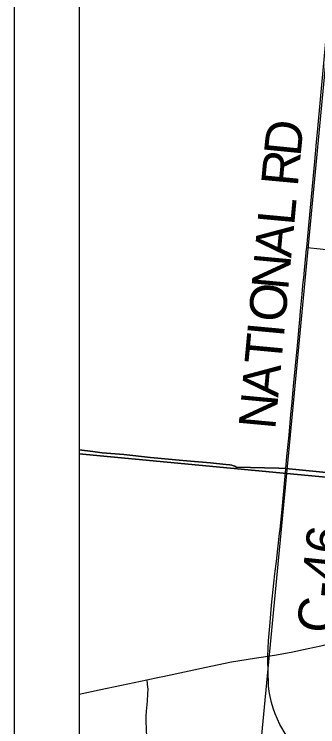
# Model space of a CAD drawing. Extents: x 0 to 34, y 0 to 22.
# Drawn here: x 22.416 to 22.884, y 14.548 to 15.645 of the extents above; entities that cross this region are included whole.
import ezdxf

# ---------------------------------------------------------------- set-up
doc = ezdxf.new("R2010")
doc.units = 0
for name, color, linetype in [('GM_X_City_Street', 7, 'Continuous'), ('GM_X_County_Road', 7, 'Continuous'), ('GM_X_County_Road_Text', 7, 'Continuous'), ('GM_X_Section', 7, 'Continuous'), ('SH_Border', 7, 'Continuous'), ('SH_Data', 7, 'Continuous')]:
    doc.layers.add(name, color=color, linetype=linetype)

msp = doc.modelspace()

# ---------------------------------------------------------------- linework, layer by layer
at = {"layer": 'GM_X_City_Street'}
for points in [[(22.867, 15.2862), (22.8729, 15.2855), (22.8828, 15.2843), (22.9172, 15.281)], [(22.6217, 14.4767), (22.6219, 14.4866), (22.6213, 14.5124), (22.6206, 14.5331), (22.6202, 14.5418), (22.6196, 14.5585), (22.6195, 14.5635), (22.6202, 14.5718), (22.6215, 14.5873), (22.6222, 14.5984), (22.6225, 14.6055), (22.6222, 14.6089), (22.6218, 14.6126), (22.6215, 14.6158), (22.6208, 14.6201)]]:
    msp.add_lwpolyline(points, dxfattribs=at)
at = {"layer": 'GM_X_County_Road'}
msp.add_line((22.6208, 14.6201), (22.6395, 14.6241), dxfattribs=at)
for points in [[(22.5164, 15.9857), (22.5164, 14.9679), (22.8365, 14.9377), (22.9324, 15.949), (22.9154, 15.9508)], [(22.5164, 14.9679), (22.5164, 13.9665), (22.7413, 13.9434), (22.8365, 14.9377)]]:
    msp.add_lwpolyline(points, close=True, dxfattribs=at)
for points in [[(22.8774, 15.3968), (22.8793, 15.4185), (22.8819, 15.4482), (22.8839, 15.4692), (22.8924, 15.5589), (22.8982, 15.6202), (22.8983, 15.6233), (22.8985, 15.6264), (22.8988, 15.6319)], [(22.867, 15.2862), (22.8701, 15.3199), (22.8774, 15.3968)], [(22.8629, 15.2442), (22.863, 15.2452), (22.8668, 15.284), (22.867, 15.2862)], [(22.86, 15.2139), (22.8612, 15.2275), (22.8629, 15.2442)], [(22.8569, 15.1806), (22.8576, 15.1886), (22.86, 15.2139)], [(22.8467, 15.0726), (22.8526, 15.1349), (22.8569, 15.1806)], [(22.8444, 15.047), (22.8445, 15.048), (22.8467, 15.0726)], [(22.8348, 14.945), (22.8366, 14.9642), (22.8397, 14.997), (22.8426, 15.0286), (22.8444, 15.047)], [(22.8252, 14.8453), (22.8259, 14.8522), (22.8289, 14.8825), (22.8348, 14.945)], [(22.8178, 14.7832), (22.8182, 14.7873), (22.8202, 14.8021), (22.8226, 14.822), (22.8252, 14.8453)], [(22.809, 14.6915), (22.8105, 14.7081), (22.8129, 14.7348), (22.8162, 14.7688), (22.8178, 14.7832)], [(22.8071, 14.6565), (22.8077, 14.6685), (22.8083, 14.6798), (22.809, 14.6915)], [(22.8071, 14.6565), (22.8174, 14.6581), (22.8432, 14.6627), (22.8691, 14.668), (22.8887, 14.6724), (22.9141, 14.6783)], [(22.6395, 14.6241), (22.6454, 14.6253), (22.7195, 14.6411), (22.7513, 14.6475), (22.7865, 14.6534), (22.8071, 14.6565)], [(22.8436, 14.5223), (22.8354, 14.5347), (22.8257, 14.5512), (22.8219, 14.5593), (22.8186, 14.5675), (22.8154, 14.5765), (22.8129, 14.585), (22.8107, 14.5944), (22.8093, 14.6019), (22.8083, 14.6109), (22.8079, 14.6172), (22.8078, 14.6273), (22.8071, 14.6565)], [(22.5164, 14.5981), (22.5474, 14.6044), (22.5818, 14.6117), (22.6208, 14.6201)]]:
    msp.add_lwpolyline(points, dxfattribs=at)
at = {"layer": 'GM_X_Section'}
for points in [[(22.9324, 15.949), (23.8855, 15.856), (23.9052, 15.8546), (23.8123, 14.8466), (22.8365, 14.9377)], [(23.8123, 14.8466), (23.731, 13.8445), (22.7413, 13.9434), (22.8365, 14.9377)]]:
    msp.add_lwpolyline(points, close=True, dxfattribs=at)
at = {"layer": 'SH_Border'}
for points in [[(22.5164, 19.0318), (22.5164, 14.9743), (22.5375, 14.9716), (22.5519, 14.9698), (22.5854, 14.9669), (22.6262, 14.9627), (22.676, 14.958), (22.6942, 14.9563), (22.7189, 14.954), (22.7424, 14.9517), (22.7484, 14.951), (22.7514, 14.9505), (22.7541, 14.9498), (22.7561, 14.949), (22.7581, 14.9478), (22.8238, 14.9459), (22.8346, 14.9455), (23.0779, 14.9215), (23.5285, 14.8877), (23.8146, 14.8663)], [(23.8146, 14.8663), (23.5285, 14.8877), (23.0779, 14.9215), (22.8346, 14.9455), (22.8238, 14.9459), (22.7581, 14.9478), (22.7561, 14.949), (22.7541, 14.9498), (22.7514, 14.9505), (22.7484, 14.951), (22.7424, 14.9517), (22.7189, 14.954), (22.6942, 14.9563), (22.676, 14.958), (22.6262, 14.9627), (22.5854, 14.9669), (22.5519, 14.9698), (22.5375, 14.9716), (22.5164, 14.9743), (22.5164, 13.4618)]]:
    msp.add_lwpolyline(points, dxfattribs=at)
at = {"layer": 'SH_Data'}
for p, q in [((22.4164, 20.3618), (22.4164, 13.3618)), ((22.5164, 20.2618), (22.5164, 13.4618))]:
    msp.add_line(p, q, dxfattribs=at)
msp.add_lwpolyline([(22.5164, 19.0318), (22.5164, 13.4618), (29.3164, 13.4618)], dxfattribs=at)

# ---------------------------------------------------------------- texts
at = {"layer": 'GM_X_County_Road_Text'}
for s, height, rotation, p in [('D', 0.0568, 84.2604, (22.8574, 15.4251)), ('R', 0.0568, 84.6902, (22.8531, 15.3788)), ('L', 0.0568, 84.6954, (22.8476, 15.319)), ('A', 0.0568, 84.6961, (22.843, 15.2692)), ('N', 0.0568, 84.6941, (22.8383, 15.2194)), ('O', 0.0568, 84.6939, (22.8337, 15.1697)), ('I', 0.0568, 84.6964, (22.8316, 15.1464)), ('T', 0.0568, 84.6932, (22.8276, 15.1041)), ('A', 0.0568, 84.697, (22.823, 15.0543)), ('N', 0.0568, 84.6939, (22.8184, 15.0045)), ('C-46', 0.05682, 83.9944, (22.908, 14.69))]:
    msp.add_text(s, height=height, rotation=rotation, dxfattribs=at).set_placement(p)

doc.saveas('drawing.dxf')
